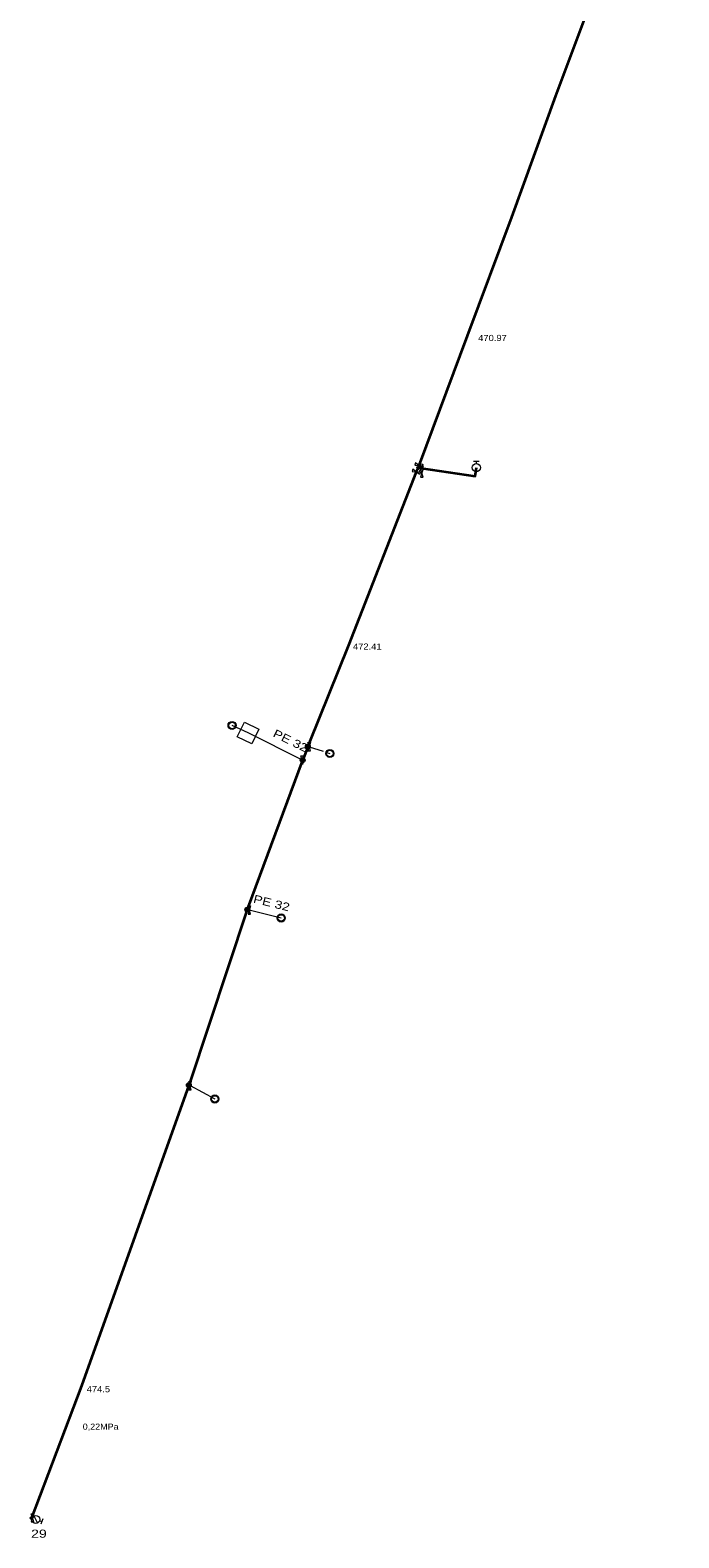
# Model space of a CAD drawing. Extents: x -687671 to -687504, y -1079137 to -1078766.
# Drawn here: x -687671.5 to -687591.5, y -1079136.9 to -1078951.3 of the extents above; entities that cross this region are included whole.
import ezdxf
from ezdxf.enums import TextEntityAlignment as Align

# ---------------------------------------------------------------- set-up
doc = ezdxf.new("R2010")
doc.units = 0
doc.header["$LTSCALE"] = 0.3
doc.linetypes.add('DOTTED', pattern=[1.5, 0.3, -1.2])
doc.linetypes.add('LONG_DASHED', pattern=[7.5, 6, -1.5])
for name, color, linetype, lineweight in [('10', 7, 'Continuous', 13), ('12', 7, 'Continuous', 13), ('35', 7, 'Continuous', 35), ('36', 7, 'LONG_DASHED', 35), ('50', 7, 'Continuous', 13), ('51', 7, 'LONG_DASHED', 13), ('63', 7, 'Continuous', 13)]:
    doc.layers.add(name, color=color, linetype=linetype, lineweight=lineweight)
for name, color, linetype in [('18', 7, 'Continuous'), ('19', 7, 'Continuous'), ('2', 7, 'Continuous'), ('3', 7, 'Continuous')]:
    doc.layers.add(name, color=color, linetype=linetype)

msp = doc.modelspace()

# ---------------------------------------------------------------- linework, layer by layer
at = {"layer": '10'}
for p, q in [((-687616.83, -1079004.4), (-687616.13, -1079004.4)), ((-687616.48, -1079004.7), (-687616.48, -1079004.4)), ((-687670.997, -1079134.216), (-687670.565, -1079135.117)), ((-687670.309, -1079134.833), (-687670.026, -1079134.933)), ((-687669.91, -1079134.602), (-687670.143, -1079135.263))]:
    msp.add_line(p, q, dxfattribs=at)
for points in [[(-687624.41, -1079005.668), (-687623.37, -1079005.752), (-687623.479, -1079006.032), (-687624.301, -1079005.388)], [(-687624.076, -1079004.909), (-687623.034, -1079004.977), (-687623.139, -1079005.258), (-687623.971, -1079004.628)], [(-687623.225, -1079005.767), (-687623.375, -1079004.733), (-687623.078, -1079004.777), (-687623.522, -1079005.723)], [(-687623.047, -1079006.358), (-687623.347, -1079005.358), (-687623.047, -1079005.358), (-687623.347, -1079006.358)], [(-687643.261, -1079037.406), (-687644.145, -1079039.2), (-687645.939, -1079038.316), (-687645.055, -1079036.522)], [(-687671.019, -1079134.963), (-687671.319, -1079133.963), (-687671.019, -1079133.963), (-687671.319, -1079134.963)]]:
    msp.add_lwpolyline(points, close=True, dxfattribs=at)
for centre in [(-687616.48, -1079005.2), (-687670.781, -1079134.668)]:
    msp.add_circle(centre, 0.5, dxfattribs=at)
at = {"layer": '12'}
for centre, radius in [((-687623.6501, -1079005.1985), 0.15), ((-687623.6501, -1079005.1985), 0.075), ((-687646.58, -1079036.93), 0.5), ((-687646.58, -1079036.93), 0.4), ((-687637.2414, -1079039.5457), 0.3), ((-687637.2414, -1079039.5457), 0.2), ((-687637.2414, -1079039.5457), 0.1), ((-687634.528, -1079040.378), 0.5), ((-687634.528, -1079040.378), 0.4), ((-687637.8875, -1079041.2073), 0.3), ((-687637.8875, -1079041.2073), 0.2), ((-687637.8875, -1079041.2073), 0.1), ((-687644.7049, -1079059.6047), 0.3), ((-687644.7049, -1079059.6047), 0.2), ((-687644.7049, -1079059.6047), 0.1), ((-687640.52, -1079060.63), 0.5), ((-687640.52, -1079060.63), 0.4), ((-687651.9045, -1079081.1988), 0.3), ((-687651.9045, -1079081.1988), 0.2), ((-687651.9045, -1079081.1988), 0.1), ((-687648.71, -1079082.91), 0.5), ((-687648.71, -1079082.91), 0.4), ((-687671.31, -1079134.49), 0.15), ((-687671.31, -1079134.49), 0.075)]:
    msp.add_circle(centre, radius, dxfattribs=at)
at = {"layer": '35'}
msp.add_line((-687623.555, -1079004.943), (-687623.65, -1079005.199), dxfattribs=at)
for points in [[(-687591.529, -1078918.576), (-687593.89, -1078925.31), (-687601.42, -1078945.26), (-687606.74, -1078959.45), (-687612.17, -1078974.38), (-687617.62, -1078988.97), (-687623.555, -1079004.943)], [(-687623.65, -1079005.199), (-687623.74, -1079005.44), (-687623.89, -1079005.71)], [(-687623.3, -1079005.25), (-687616.63, -1079006.24), (-687616.48, -1079005.2)], [(-687623.89, -1079005.71), (-687632.23, -1079027.05), (-687637.06, -1079039.08), (-687637.241, -1079039.546)], [(-687637.241, -1079039.546), (-687637.87, -1079041.16), (-687637.888, -1079041.207)], [(-687637.888, -1079041.207), (-687644.62, -1079059.35), (-687644.705, -1079059.605)], [(-687644.705, -1079059.605), (-687651.83, -1079080.99), (-687651.905, -1079081.199)], [(-687651.905, -1079081.199), (-687665.12, -1079118.22), (-687671.31, -1079134.49)]]:
    msp.add_lwpolyline(points, dxfattribs=at)
at = {"layer": '36'}
msp.add_line((-687623.3, -1079005.25), (-687623.65, -1079005.199), dxfattribs=at)
at = {"layer": '36', "linetype": 'DOTTED'}
msp.add_lwpolyline([(-687671.31, -1079134.49), (-687671.169, -1079134.463), (-687670.781, -1079134.667)], dxfattribs=at)
at = {"layer": '50'}
for p, q in [((-687637.97, -1079041.17), (-687637.888, -1079041.207)), ((-687644.46, -1079059.65), (-687644.705, -1079059.605)), ((-687644.46, -1079059.65), (-687640.52, -1079060.63)), ((-687651.75, -1079081.27), (-687651.905, -1079081.199)), ((-687651.75, -1079081.27), (-687648.71, -1079082.91))]:
    msp.add_line(p, q, dxfattribs=at)
msp.add_lwpolyline([(-687637.97, -1079041.17), (-687644.6, -1079037.861), (-687646.58, -1079036.93)], dxfattribs=at)
at = {"layer": '51'}
msp.add_lwpolyline([(-687637.241, -1079039.546), (-687637.08, -1079039.55), (-687634.528, -1079040.378)], dxfattribs=at)
at = {"layer": '63'}
for points in [[(-687637.82, -1079041.67), (-687638.12, -1079040.67), (-687637.82, -1079040.67), (-687638.12, -1079041.67)], [(-687636.93, -1079040.05), (-687637.23, -1079039.05), (-687636.93, -1079039.05), (-687637.23, -1079040.05)], [(-687644.31, -1079060.15), (-687644.61, -1079059.15), (-687644.31, -1079059.15), (-687644.61, -1079060.15)], [(-687651.6, -1079081.77), (-687651.9, -1079080.77), (-687651.6, -1079080.77), (-687651.9, -1079081.77)]]:
    msp.add_lwpolyline(points, close=True, dxfattribs=at)

# ---------------------------------------------------------------- texts
at = {"layer": '18', "width": 1.3}
msp.add_text('29', height=1, dxfattribs=at).set_placement((-687670.375, -1079136.919), align=Align.CENTER)
at = {"layer": '19', "width": 1.25}
for rotation, p in [(333.782, (-687639.5884, -1079039.2588)), (346.032, (-687641.8252, -1079059.2741))]:
    msp.add_text('PE 32', height=1, rotation=rotation, dxfattribs=at).set_placement(p, align=Align.CENTER)
at = {"layer": '2', "width": 1.1}
msp.add_text('0,22MPa', height=0.75, dxfattribs=at).set_placement((-687664.98, -1079123.621))
at = {"layer": '3', "width": 1.15}
for s, p in [('470.97', (-687614.491, -1078989.607)), ('472.41', (-687629.916, -1079027.599)), ('474.5', (-687663.05, -1079119.008))]:
    msp.add_text(s, height=0.75, dxfattribs=at).set_placement(p, align=Align.CENTER)

doc.saveas('drawing.dxf')
